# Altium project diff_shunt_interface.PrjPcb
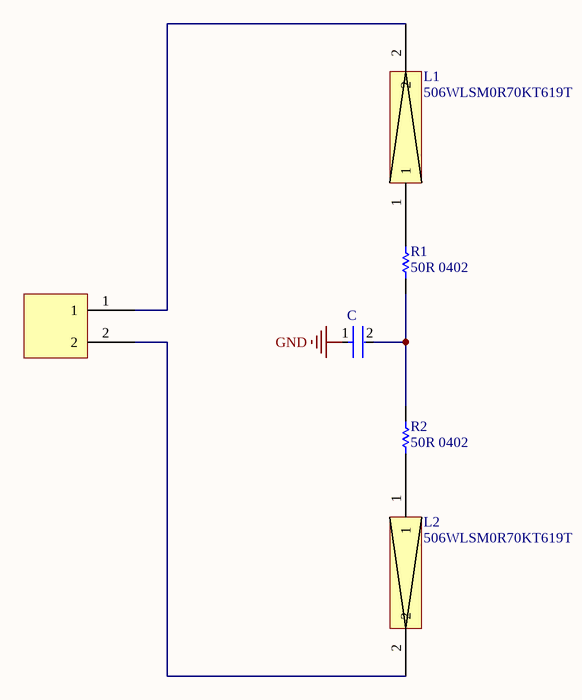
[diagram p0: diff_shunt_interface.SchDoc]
1 sheet, 6 parts. Net scope: global (net labels, ports and power ports of the same name join across sheets).
Board file: diff_shunt_interface.PcbDoc

## Sheet diff_shunt_interface.SchDoc
size A; SheetNumber: 1; SheetTotal: 1

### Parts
C  CBR08C470FAGAC  [FP-CBR08C-MFG]  (value not drawn)
L1  506WLSM0R70KT619T  [506WLS]
L2  506WLSM0R70KT619T  [506WLS]
R1  50R 0402  [RESC1005X35X20LL05T10]
R2  50R 0402  [RESC1005X35X20LL05T10]
wb  wirebondpads  [wirebondPads]  (value not drawn)

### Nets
GND: C.1
NetC_2: C.2 R1.1 R2.2
NetL1_1: L1.1 R1.2
NetL1_2: L1.2 wb.1
NetL2_1: L2.1 R2.1
NetL2_2: L2.2 wb.2

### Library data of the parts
C = CMP-03020-025427-1: CAP CER 47PF 250V C0G/NP0 0805; Manufacturer: KEMET; Temperature Coefficient: 30ppm/°C; Tolerance: 0.01; Description: CBR0805 47 pF C0G 30ppm/°C 1.00% 250 V; Temperature Characteristic: C0G
L1 L2 = 506WLSM0R70KT619T: coilcraft 700nH
R1 R2 = CMP-2002-03144-1: Part Number: CPF0402B15K8E1; Manufacturer: TE Connectivity / AMP
wb = wirebondpads: bond pad double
